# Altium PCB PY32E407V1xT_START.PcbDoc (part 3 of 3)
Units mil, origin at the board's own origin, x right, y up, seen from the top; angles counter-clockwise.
Board outline 1968.43 x 4717 mil, 2 copper layers (Top Layer, Bottom Layer), stack 21 mil thick; 210 components, 217 nets, 824 pads, 371 vias.
Unrouted connection lines stored in the file: 1.
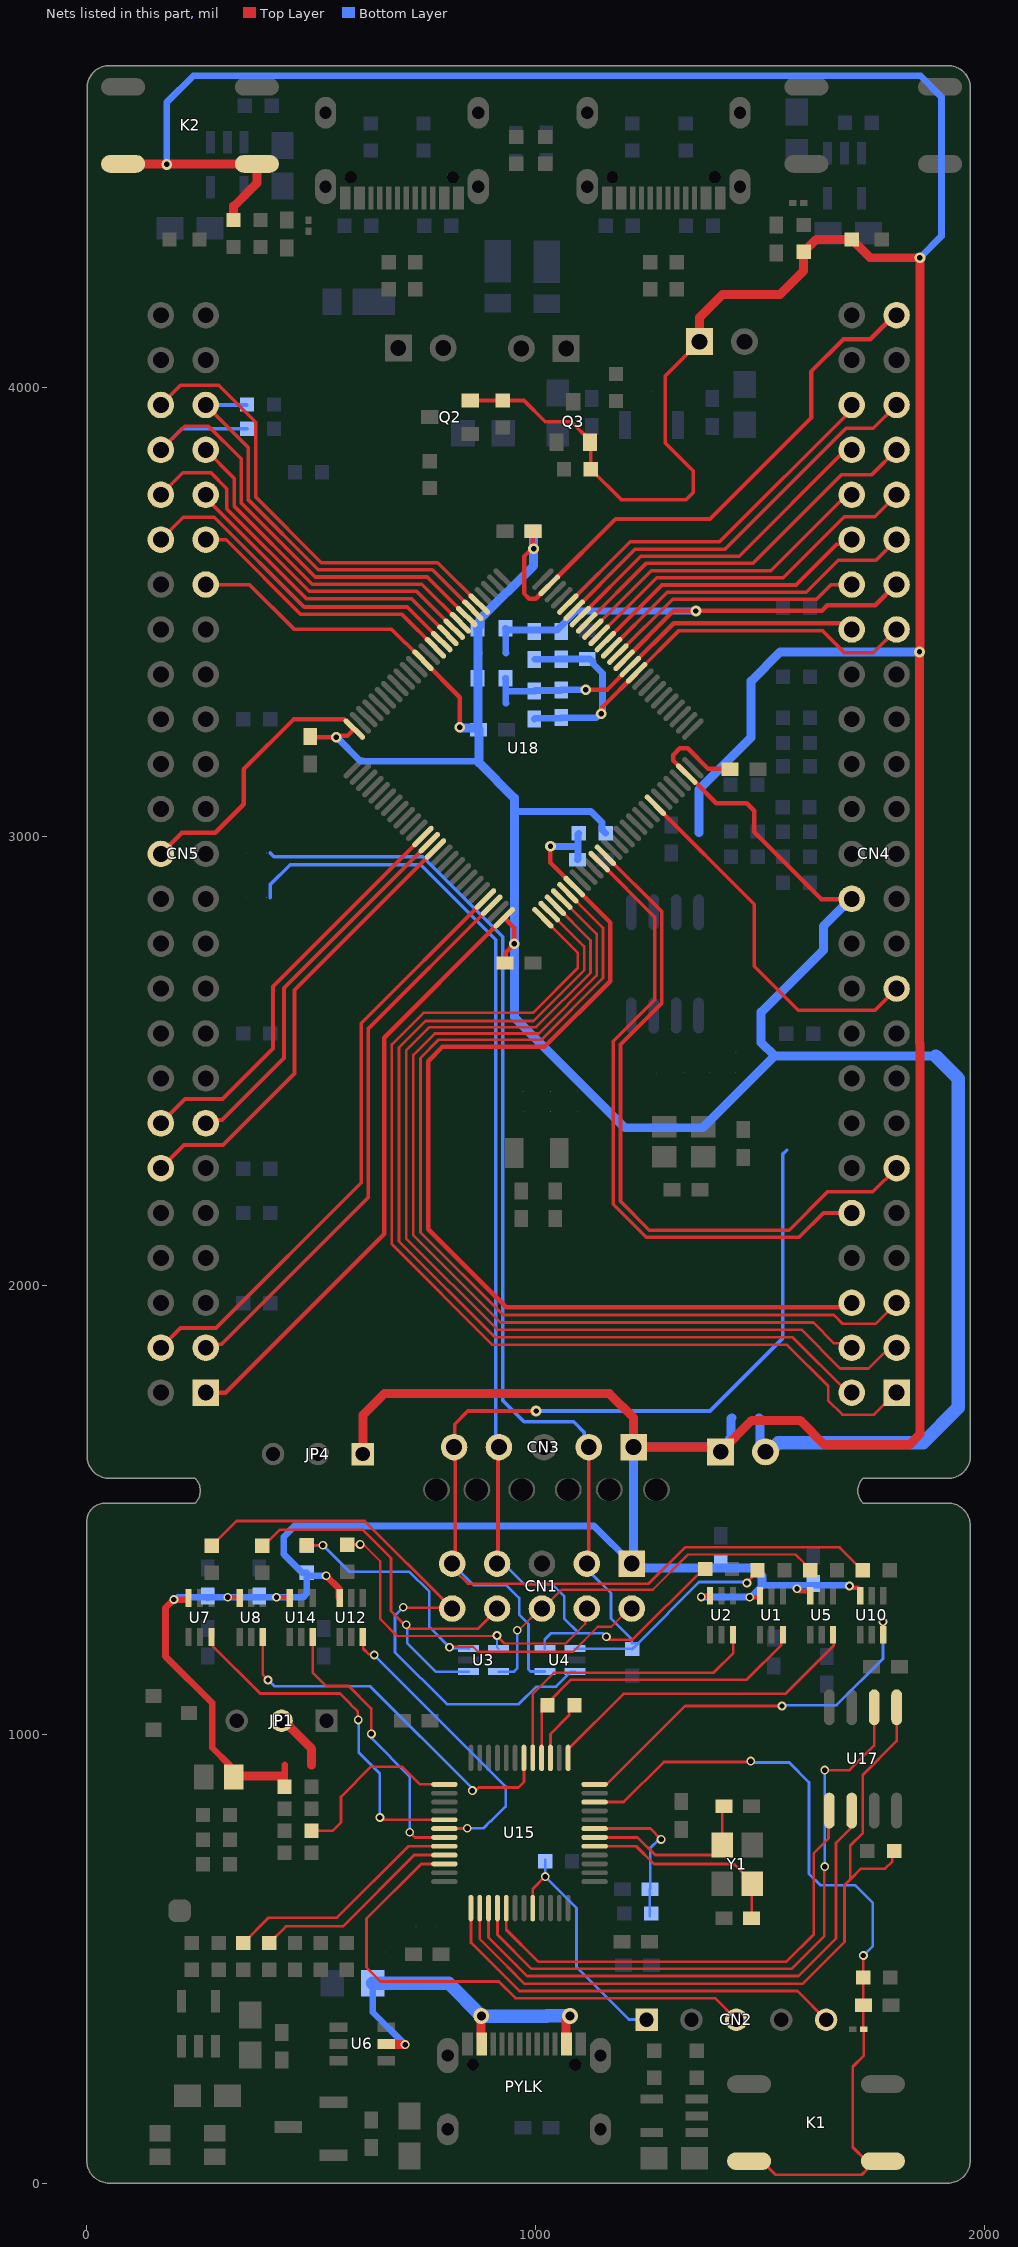
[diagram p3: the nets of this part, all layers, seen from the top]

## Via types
v1: diameter 24, hole 12, Top Layer to Bottom Layer, tented both sides, 208 vias
v2: diameter 19.68, hole 11.81, Top Layer to Bottom Layer, tented both sides, 106 vias
v3: diameter 19.68, hole 11.81, Top Layer to Bottom Layer, 37 vias
v4: diameter 35, hole 20, Top Layer to Bottom Layer, tented both sides, 16 vias
v5: diameter 30, hole 15, Top Layer to Bottom Layer, tented both sides, 2 vias
v6: diameter 40, hole 20, Top Layer to Bottom Layer, tented both sides, 2 vias

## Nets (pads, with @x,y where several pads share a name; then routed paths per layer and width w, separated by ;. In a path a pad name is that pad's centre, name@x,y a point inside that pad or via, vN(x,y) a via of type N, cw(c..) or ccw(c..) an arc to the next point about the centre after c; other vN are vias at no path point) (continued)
PD5: CN5.14 U18.87 | length 931.3
  Top Layer w9: CN5.14@165,2361 165,2364 168,2364 219,2415 302.59,2415 415.27,2527.68 415.27,2666.11 U18.87@748.9,2999.74
PD6: CN5.13 U18.88 | length 847.8
  Top Layer w9: CN5.13@265,2361 272.09,2368.09 300.76,2368.09 439.48,2506.82 439.48,2662.48 U18.88@762.82,2985.82
PD7: CN5.12 U18.89 | length 1015.2
  Top Layer w9: CN5.12@165,2261 217,2313 303.87,2313 462.52,2471.64 462.52,2657.68 U18.89@776.74,2971.9
PD8: CN5.46 U18.55 | length 1026.9
  Top Layer w8: CN5.46@165,3961 209,4005 293.71,4005 376.11,3922.6 376.11,3755.99 522.27,3609.84 781.87,3609.84 U18.55@874.17,3517.54
PD9: CN5.45 R81.1 U18.56 | length 944
  Top Layer w8: CN5.45@265,3961 360.11,3865.89 360.11,3749.36 515.64,3593.84 770.04,3593.84 U18.56@860.26,3503.62
  Bottom Layer w8: CN5.45@265,3961 R81.1@356,3961
PD10: CN5.44 R97.2 U18.57 | length 1148
  Top Layer w8: CN5.44@165,3861 218,3914 271.05,3914 344.11,3840.94 344.11,3742.74 509.01,3577.84 758.2,3577.84 U18.57@846.34,3489.7
  Bottom Layer w8: CN5.44@165,3861 212,3908 R97.2@357,3908
PD11: CN5.43 U18.58 | length 763.2
  Top Layer w8: CN5.43@265,3861 328.11,3797.89 328.11,3736.11 502.38,3561.84 746.36,3561.84 U18.58@832.42,3475.78
PD12: CN5.42 U18.59 | length 844.4
  Top Layer w8: CN5.42@165,3761 213.97,3809.97 276.67,3809.97 312.11,3774.53 312.11,3729.48 495.76,3545.84 734.52,3545.84 U18.59@818.5,3461.86
PD13: CN5.41 U18.60 | length 673.4
  Top Layer w8: CN5.41@265,3761 265,3753.97 489.13,3529.84 722.69,3529.84 U18.60@804.58,3447.94
PD14: CN5.40 U18.61 | length 761.1
  Top Layer w8: CN5.40@165,3661 215.03,3711.03 284.02,3711.03 484.11,3510.93 713.75,3510.93 U18.61@790.66,3434.02
PD15: CN5.39 U18.62 | length 611.5
  Top Layer w8: CN5.39@265,3661 265.52,3660.48 310.45,3660.48 476.45,3494.48 702.35,3494.48 U18.62@776.74,3420.1
PE0: CN5.4 U18.97 | length 1345.3
  Top Layer w8: CN5.4@165,1861 209,1905 287.86,1905 611.48,2228.63 611.48,2583.93 U18.97@888.1,2860.54
PE1: CN5.3 U18.98 | length 1265.6
  Top Layer w8: CN5.3@265,1861 272.65,1868.65 300.08,1868.65 627.48,2196.05 627.48,2572.09 U18.98@902.01,2846.63
PE2: CN4.1 U18.1 | length 2395.3
  Top Layer w6: U18.1@1016.15,2818.79 1016.15,2818.11 1094,2740.26 1094,2707.45 993.55,2607 750.12,2607 679.48,2536.36 679.48,2091.47 903.48,1867.48 1560.33,1867.48 1651.56,1776.25 1651.56,1743.27 1683,1711.83 1753.46,1711.83 1777.1,1735.47 1778.47,1735.47 CN4.1@1804,1761
PE3: CN4.2 U18.2 | length 2226.9
  Top Layer w6: U18.2@1030.06,2832.7 1108,2754.77 1108,2701.65 995.35,2589 754.75,2589 695.48,2529.74 695.48,2098.09 909.29,1884.29 1572.45,1884.29 1695.74,1761 CN4.2@1704,1761
PE4: CN4.3 U18.3 | length 2315.1
  Top Layer w6: U18.3@1043.99,2846.63 1122,2768.61 1122,2695.85 1001.15,2575 763.37,2575 711.48,2523.11 711.48,2104.72 915.1,1901.1 1591.85,1901.1 1678.09,1814.86 1741.07,1814.86 1786.95,1860.74 CN4.3@1804,1861
PE5: CN4.4 U18.4 | length 2166.6
  Top Layer w6: U18.4@1057.9,2860.54 1136,2782.44 1136,2690.05 1006.95,2561 775.38,2561 727.48,2513.11 727.48,2111.35 921.73,1917.1 1618.58,1917.1 1664.92,1870.77 1694.23,1870.77 CN4.4@1704,1861
PE6: CN4.5 U18.5 | length 2255.1
  Top Layer w6: U18.5@1072.24,2874.05 1150,2796.29 1150,2684.25 1012.75,2547 784,2547 743.48,2506.48 743.48,2117.98 927.74,1933.72 1664.38,1933.72 1684,1914.09 1757.09,1914.09 CN4.5@1804,1961
PE7: CN4.38 U18.38 | length 584.9
  Top Layer w8: U18.38@1183.18,3406.18 1305.04,3528.04 1625.51,3528.04 1658.46,3561 CN4.38@1704,3561
PE8: CN4.39 U18.39 | length 758.8
  Top Layer w8: U18.39@1152.1,3402.94 1293.2,3544.04 1602.95,3544.04 1673.91,3615 1758,3615 CN4.39@1804,3661
PE9: CN4.40 U18.40 | length 642.6
  Top Layer w8: U18.40@1155.34,3434.02 1281.41,3560.04 1580.09,3560.04 1671.28,3651.23 1694.23,3651.23 CN4.40@1704,3661
PE10: CN4.41 U18.41 | length 792.3
  Top Layer w8: U18.41@1141.42,3447.94 1269.52,3576.04 1551.46,3576.04 1687.42,3712 1755,3712 CN4.41@1804,3761
PE11: CN4.42 U18.42 | length 724.7
  Top Layer w8: U18.42@1110.34,3444.7 1257.69,3592.04 1523.74,3592.04 1692.7,3761 CN4.42@1704,3761
PE12: CN4.43 U18.43 | length 849.9
  Top Layer w8: U18.43@1113.64,3475.78 1245.9,3608.04 1483.57,3608.04 1681.53,3806 1749,3806 CN4.43@1804,3861
PE13: CN4.44 U18.44 | length 758.1
  Top Layer w8: U18.44@1099.66,3489.7 1234.01,3624.04 1453.3,3624.04 1690.26,3861 CN4.44@1704,3861
PE14: CN4.45 U18.45 | length 932
  Top Layer w8: U18.45@1068.58,3486.46 1222.16,3640.04 1422.26,3640.04 1691.49,3909.27 1752.27,3909.27 CN4.45@1804,3961
PE15: CN4.46 U18.46 | length 821.9
  Top Layer w8: U18.46@1071.88,3517.54 1210.38,3656.04 1409.46,3656.04 1704,3950.58 CN4.46@1704,3961
PF2: CN4.19 U18.19 | length 821.9
  Top Layer w8: U18.19@1270.35,3065.49 1486.87,2848.97 1486.87,2710.72 1584.59,2613 1756,2613 CN4.19@1804,2661
PF3: CN4.10 U18.10 | length 1437.1
  Top Layer w8: U18.10@1141.42,2944.06 1265.25,2820.23 1265.25,2770.06 1265.24,2697.91 1265.25,2636.18 1173,2543.93 1173,2180.37 1246.61,2106.76 1586.76,2106.76 1641,2161 CN4.10@1704,2161
PF4: CN4.11 U18.11 | length 1560.2
  Top Layer w8: U18.11@1155.34,2957.98 1281.25,2832.08 1281.25,2763.43 1281.24,2704.54 1281.25,2628.75 1189,2536.5 1189,2187 1253.24,2122.76 1564.76,2122.76 1650.11,2208.11 1751.11,2208.11 CN4.11@1804,2261
PYLK_BOOT0: CN2.1 R27.1 U15.44 | length 552.1
  Top Layer w6: U15.44@993.53,612.68 993.53,655.07 v2(1021.21,682.75)
  Bottom Layer w6: R27.1@1021.21,719.9 v2(1021.21,682.75) 1091,612.96 1091,481 1207.51,364.49 CN2.1@1245.51,364.49
PYLK_KEY: C5.2 K1.1 K1.2 R15.1 U11.1 U15.10 | length 1851.6
  Top Layer w6: U15.10@1131.32,848.9 1196.14,848.9 1285.44,938.2 1477.2,938.2 v2(1479,940) ; K1.2@1475.55,49 1504.25,49 1534.5,18.75 1726.36,18.75 1738.02,30.41 1738.02,34.51 K1.1@1752.51,49 ; R15.1@1727,453 1730,450 C5.2@1730,396 1730,343.54 U11.1@1730.54,343 1730.54,283.54 1706.3,259.3 1706.3,80 1737.3,49 K1.1@1752.51,49 ; R15.1@1729.77,458 1730,458.23 v2(1730,507) ; K1.1@1773.55,49 K1.1@1752.51,49
  Bottom Layer w6: v2(1479,940) 1482.06,936.94 1491.62,936.94 1491.69,936.88 1564.92,936.88 1609,892.8 1609,688.76 1633.9,663.86 1711.04,663.86 1751,623.9 1751,528 v2(1730,507)
PYLK_NRST: C23.2 R35.1 U15.7 | length 341.9
  Top Layer w6: U15.7@1131.32,789.84 1255.36,789.84 v2(1279.4,765.8)
  Bottom Layer w6: R35.1@1254.12,595 1254.12,654 C23.2@1255.12,655 1255.12,746 1274.92,765.8 v2(1279.4,765.8)
PYLK_OSCIN: C18.2 U15.5 Y1.3 | length 465.6
  Top Layer w6: U15.5@1131.32,750.47 1224.05,750.47 1263.42,711.1 1442.11,711.1 1482.59,670.63 Y1.3@1482.59,666.69 1481.12,665.22 C18.2@1481.12,590
PYLK_OSCOUT: C24.2 U15.6 Y1.1 | length 399.8
  Top Layer w6: U15.6@1131.32,770.16 1226.99,770.16 1266.36,730.79 1396.03,730.79 1415.66,750.41 Y1.1@1415.66,753.31 1415.66,836.54 C24.2@1419.12,840
PYLK_SPI_CS: R34.1 U15.38 U17.1 | length 1667.6
  Top Layer w5: U15.38@875.42,612.68 875.42,543.62 936.66,482.38
  Top Layer w6: 936.66,482.38 974.95,444.09 1594.51,444.09 1687.88,537.47 1687.88,663.88 1700.77,676.77 ; R34.1@1799,740 1794.62,735.62 1794.62,716.69 1778.36,700.42 1724.42,700.42 1700.77,676.77 ; U17.1@1804,1060 1804,985 1728.69,909.69 1728.69,780.01 1700.77,752.09 1700.77,676.77
PYLK_SPI_MISO: U15.40 U17.2 | length 1437.2
  Top Layer w6: U15.40@914.79,612.68 914.79,553.3 990.8,477.3 1570,477.3 1642.9,550.2 1642.9,703.9 v2(1644,705) ; v2(1644,920) 1699,920 1754,975 U17.2@1754,1060
  Bottom Layer w6: v2(1644,705) v2(1644,920)
PYLK_SPI_MOSI: U15.41 U17.5 | length 1077.9
  Top Layer w6: U15.41@934.47,612.68 934.47,564.49 1005.66,493.3 1558.42,493.3 1619.53,554.41 1619.53,735.09 1652.13,767.69 1652.13,828.13 U17.5@1654,830
PYLK_SPI_SCK: U15.39 U17.6 | length 1208.9
  Top Layer w6: U15.39@895.1,612.68 895.1,547.36 955.32,487.14 981.17,461.3 1585.07,461.3 1669.21,545.44 1669.21,758.06 1700.94,789.79 1700.94,826.94 U17.6@1704,830
SWD_SCK: CN2.5 U15.37 | length 939.3
  Top Layer w6: U15.37@855.73,612.68 855.73,535.75 963.48,428 1583,428 CN2.5@1647,364
SWD_SDA: CN2.3 U15.34 | length 1204.8
  Top Layer w6: U15.34@796.68,711.1 745.11,711.1 623.05,589.04 623.05,480.71 654.57,449.2 917.75,449.2 954.95,412 1399,412 CN2.3@1447,364
T_RESET: CN1.9 CN3.5 R17.2 R39.1 U4.4 | length 2927.6
  Top Layer w6: CN1.9@821.78,1362.78 849.2,1335.36 1251.91,1335.36 1332.99,1416.44 1677.06,1416.44 R17.2@1728.49,1365
  Top Layer w8: CN1.9@814,1380 821,1387 821,1636.82 CN3.5@818.26,1639.56 819.51,1640.82 819.51,1690.51 849,1720 v1(1001,1720)
  Bottom Layer w6: CN1.9@814,1380 862.22,1331.78 935.02,1331.78 963.1,1303.69 963.1,1266.42 984.15,1245.37 984.15,1144.31 988.61,1139.85 1020.09,1139.85 U4.4@1020.54,1139.41
  Bottom Layer w8: CN1.9@814,1380 CN1.9@823.04,1389.04 ; CN3.5@818.26,1639.56 CN3.5@823.04,1634.78 ; v1(1001,1720) 1388.26,1720 1550,1881.74 1550,2291.74 R39.1@1559.26,2301
T_RESETa: U10.3 U15.12 | length 870.1
  Top Layer w6: U15.12@1131.32,888.27 1157.79,888.27 1332.47,1062.96 1420.53,1062.96 v2(1548.91,1062.96) ; v2(1773.82,1250.7) 1774.08,1250.44 U10.3@1774.08,1221.69
  Bottom Layer w6: v2(1548.91,1062.96) 1550.65,1064.7 1670.4,1064.7 1773.82,1168.11 v2(1773.82,1250.7)
T_RTCK_DTRa: U5.3 U15.13 | length 731.2
  Top Layer w6: U15.13@1072.27,947.32 1072.27,966.57 1195.7,1090 1555.99,1090 1664.18,1198.19 1664.18,1220.16 U5.3@1662.66,1221.69
T_RTCK_VCP_DTR: CN1.6 R9.2 U3.5 | length 868.3
  Top Layer w5: v2(958.81,1231.67) 962.24,1231.67 1010.57,1280 CN1.6@1014,1280 1015.63,1280 1057.49,1321.86 1260.73,1321.86 1339.3,1400.44 1578.98,1400.44 1599.35,1380.07 1599.35,1377 R9.2@1611.35,1365
  Bottom Layer w6: U3.5@917.46,1139.41 951.51,1139.41 958.81,1146.71 v2(958.81,1231.67)
T_TCK_SWCLK: CN1.7 CN3.4 R6.2 R38.1 U4.5 | length 2745.1
  Top Layer w6: CN1.7@919,1390 CN1.7@920.35,1391.35 ; v2(1157.5,1217.32) 1164.14,1210.69 1215.96,1210.69 1370.28,1365 R6.2@1377.06,1365
  Top Layer w8: CN1.7@914,1380 916.13,1382.13 916.13,1637.43 CN3.4@918.26,1639.56
  Bottom Layer w6: CN1.7@921.5,1387.5 974.47,1334.53 1036.65,1334.53 1063.6,1307.57 1063.6,1257.54 1096.14,1225 ; U4.5@1020.54,1190.59 1020.54,1211.54 1034,1225 1096.14,1225 ; v2(1157.5,1217.32) 1149.82,1225 1096.14,1225
  Bottom Layer w8: 409,2864 409,2892.89 453.11,2937 743.71,2937 910.9,2769.82 910.9,1873.73 911,1873.63 911,1841.37 910.9,1841.27 910.9,1646.93 CN3.4@918.26,1639.56 CN3.4@916.79,1638.1 ; CN1.7@914,1380 CN1.7@916.79,1382.79
T_TCK_SWCLKa: U2.3 U15.17 | length 668.1
  Top Layer w5: U15.17@993.53,947.32 993.53,1089.76 1040.77,1137
  Top Layer w6: 1040.77,1137 1146.62,1137 1396.43,1137 1440.41,1180.98 1440.41,1221.08 U2.3@1439.8,1221.69
T_TDI_VCP_TX: CN1.4 R21.2 U3.4 | length 783.1
  Top Layer w5: R21.2@580.63,1422.11 616.9,1422.11 653.54,1385.48 653.54,1256.62 691.29,1218.86 v2@914,1218.86 ; R21.2@580.63,1425.11 R21.2@582.13,1423.61 ; v2@914.02,1218.86 930.78,1202.11 1066.76,1202.11 1110.56,1245.9 1110.56,1276.56 CN1.4@1114,1280
  Bottom Layer w5: v2@914.06,1219.94 914.06,1194 U3.4@917.46,1190.59
  other v2: 914,1220
  other v3: 608.96,1422.98
T_TDI_VCP_TXa: U12.3 U15.30 | length 672.4
  Top Layer w6: U12.3@614.71,1216.69 615.93,1215.47 615.93,1190.37 628.24,1178.06 638.56,1178.06 v2(640.31,1176.31) ; U15.30@796.68,789.84 847.02,789.84 v2(847.76,790.58)
  Bottom Layer w6: v2(640.31,1176.31) 933.09,883.53 933.09,838.92 900.56,806.38 899.71,806.38 883.91,790.58 v2(847.76,790.58)
T_TDO_SWO: CN1.10 R12.2 U4.3 | length 1333.3
  Top Layer w6: R12.2@278.66,1420.08 333.47,1474.9 619.1,1474.9 CN1.10@807.51,1286.49 ; v2(704.87,1282.75) 705.54,1282.08 803.1,1282.08 CN1.10@807.51,1286.49 ; CN1.10@814,1280 CN1.10@807.51,1286.49
  Bottom Layer w6: v2(704.87,1282.75) 686.83,1264.72 686.83,1182.08 802.06,1066.86 962.29,1066.86 1001.42,1105.99 1045.45,1105.99 1078.88,1139.41 U4.3@1087.46,1139.41 U4.3@1085.15,1137.1
T_TDO_SWOa: U7.3 U15.29 | length 807.7
  Top Layer w6: U7.3@278.14,1216.69 278.14,1198.86 386.46,1090.54 564.08,1090.54 570.63,1084 571.01,1084 588,1067.01 588,1066.63 603.93,1050.7 603.93,1032.69 v2(604.62,1032) ; v2(652.88,814.33) 657.68,809.53 740.55,809.53 U15.29@796.68,809.53
  Bottom Layer w6: v2(604.62,1032) 605.95,1030.68 605.95,958.93 652.88,912 v2(652.88,814.33)
T_TMS_SWDIO: CN1.3 CN3.2 R2.2 R37.1 R82.2 U4.1 | length 2855.4
  Top Layer w6: CN1.3@1118.37,1366.19 CN1.3@1124.56,1360 ; v2@1470.62,1338.31 1481.21,1348.9 1481.21,1352 R2.2@1494.21,1365
  Top Layer w8: CN1.3@1114,1380 1118.26,1384.26 CN3.2@1118.26,1639.56
  Bottom Layer w6: U4.1@1087.77,1190.29 1215.29,1190.29 R82.2@1225.38,1200.38 ; CN1.3@1122.59,1359.7 1167.86,1314.42 1167.86,1257.89 1214.27,1211.49 1214.27,1203 1222.75,1203 R82.2@1225.38,1200.38 ; R82.2@1215,1190 R82.2@1225.38,1200.38 ; v2(1470.43,1337.07) 1468.25,1339.25 1364.25,1339.25 R82.2@1225.38,1200.38
  Bottom Layer w8: 409,2963 417.28,2954.72 748.62,2954.72 926.9,2776.44 926.9,1880.36 927,1880.25 927,1834.75 926.9,1834.64 926.9,1743.26 974.16,1696 1084.55,1696 1108.49,1672.06 1108.49,1649.33 CN3.2@1118.26,1639.56 CN3.2@1118,1639.3 ; CN1.3@1114,1380 CN1.3@1118,1384
T_TMS_SWDIOa: R31.1 U1.3 U15.16 | length 723.8
  Top Layer w6: U15.16@1013.21,947.32 R31.1@1013.21,1067.37 ; R31.1@1026.46,1064.37 1026.46,1068.99 1079.12,1121.65 1135.7,1121.65 1470.22,1121.65 1547.34,1198.77 1547.34,1217.8 U1.3@1551.23,1221.69
T_TMS_SWDIOa_OUT: R31.2 U15.15 | length 143.2
  Top Layer w6: U15.15@1032.9,947.32 1032.9,1000.64 1074.82,1042.56 R31.2@1074.82,1073.16
T_TRST_RTSa: U8.3 U15.18 | length 840.3
  Top Layer w6: U8.3@391.86,1216.69 391.86,1132.86 v2(403.82,1120.9) ; v2(858.92,874.35) 862.83,870.44 873.54,881.16 961.39,881.16 973.84,893.6 U15.18@973.84,947.32
  Bottom Layer w6: v2(403.82,1120.9) 417.81,1106.91 630.65,1106.91 858.92,878.64 v2(858.92,874.35)
T_TRST_VCP_RTS: CN1.8 R13.2 U3.1 | length 935
  Top Layer w6: R13.2@391.3,1420.1 394.54,1420.1 430.24,1455.8 614.25,1455.8 677.58,1392.47 677.58,1274.56 708.4,1243.73 v2(711.86,1243.73) 720.6,1235 871.67,1235 919,1282.33 CN1.8@919,1290
  Bottom Layer w6: v2(711.86,1243.73) 714,1241.6 714,1202.6 777.19,1139.41 U3.1@850.54,1139.41
T_VCP_RX: CN1.2 R22.1 R25.2 U3.3 | length 1000.9
  Top Layer w5: v2(807.97,1193.74) 809.23,1195 860.42,1195 871.45,1183.97 1082.91,1183.97 1138.3,1239.36 1168.36,1239.36 CN1.2@1219,1290
  Top Layer w6: R25.2@490.2,1420.7 525.7,1420.7 v3(526,1421) ; R25.2@490.2,1431.85 R25.2@490.32,1431.97
  Bottom Layer w6: R22.1@490,1420 491,1421 v3(526,1421) 584.72,1362.28 718.26,1362.28 763.05,1317.5 763.05,1238.66 v2(807.97,1193.74) 807.23,1193 807.23,1191.77 849.36,1191.77 U3.3@850.54,1190.59
T_VCP_RXa: U14.3 U15.31 | length 636
  Top Layer w6: U14.3@503.28,1216.69 503.28,1137.29 532.27,1108.3 582.54,1108.3 633.4,1057.43 633.4,1001.38 v2(634,1000.78) ; v2(719.4,781.75) 730.99,770.16 U15.31@796.68,770.16
  Bottom Layer w6: v2(634,1000.78) 634,991.42 719.4,906.02 v2(719.4,781.75)
TVDD: C11.2 C12.2 C13.2 C14.2 CN1.1 CN3.1 JP2.1 JP3.1 JP4.1 K2.1 K2.2 LED2_PB5.1 Q2.2 Q3.2 R14.2 R16.2 R22.2 R33.2 R50.1 R51.1 R58.1 R59.2 R95.1 R98.1 U1.6 U2.6 U5.6 U7.6 U8.6 U10.6 U12.6 U14.6 | length 12757.1
  Top Layer w6: U8.6@340.67,1303.31 U8.6@343.56,1306.2 ; U14.6@452.1,1303.31 U14.6@454.99,1306.2
  Top Layer w8: Q2.2@854.55,3971.4 854.95,3971 R95.1@927,3971 974,3971 1021,3924 1078.94,3924 1121,3881.94 Q3.2@1121,3878 1123,3876 R98.1@1123,3818 1191.06,3749.94 1334.94,3749.94 1351,3766 1351,3814 1289,3876 1289,4026 JP3.1@1365,4102
  Top Layer w10: v2(314,1305) 338.98,1305 U8.6@340.67,1303.31 ; v3@424,1305 450.41,1305 U14.6@452.1,1303.31 ; v3(1476.88,1305.09) 1498.07,1305.09 1498.16,1305 1500.05,1306.89 U1.6@1500.05,1308.31 ; v2(1582.29,1324.06) 1587.61,1318.74 1611.47,1318.74 U5.6@1611.47,1308.31 ; v2@1707.68,1326.1 1717.91,1326.1 1722.9,1321.1 U10.6@1722.9,1308.31
  Top Layer w12: v2@1369.9,1306.9 U2.6@1388.01,1306.9
  Top Layer w15: v2(194,1300) 175.66,1281.66 175.66,1173.6 279.53,1069.73 279.53,969.95 319.52,929.96 319.52,912.95 R14.2@327.46,905 R14.2@329.24,906.78 ; v2@194.63,1299.37 U7.6@226.35,1299.37 ; 437.07,906.78 441.08,902.77 ; R16.2@441.08,874.02 441.08,902.77 ; 441.08,931.52 441.08,902.77 ; v3(533.28,1353.05) 561.84,1324.49 561.84,1305 U12.6@563.53,1303.31 ; v2(1369,1306) v2@1369.9,1306.9
  Top Layer w20: K2.2@81,4498 K2.1@379,4498 379,4455 328,4404 327,4404 R59.2@327,4373 ; R14.2@329.24,906.78 437.07,906.78 ; JP4.1@615,1624.13 615,1711 663,1759 1164,1759 1218.26,1704.74 CN3.1@1218.26,1639.56 1401.56,1639.56 JP2.1@1412,1629.13 1481.87,1699 1589,1699 1643,1645 1832.77,1645 1856,1668.23 1856,2538.57 1855,2539.57 v1(1855,3411) ; JP3.1@1365,4102 1365,4156 1416,4207 1544,4207 1597,4260 R51.1@1597,4302 1625,4330 LED2_PB5.1@1704,4330 1745,4289 v1(1856,4289) v1@1856,3411
  Bottom Layer w15: v1(178,4497) 178,4635 237.49,4694.49 1857,4694.49 1904.02,4647.47 1904.02,4337.02 v1(1856,4289) ; v2(194,1300) 197.79,1300 202.67,1304.88 C14.2@267.87,1304.88 ; C14.2@269,1303.74 C14.2@267.87,1304.88 ; v2@313.88,1304.88 C14.2@267.87,1304.88 ; v2(314,1305) v3(422.77,1305) 482,1305 490,1313 R22.2@490,1353.05 ; v3(533.28,1353.05) R22.2@490,1353.05 ; CN1.1@1214,1380 1130,1464 463,1464 439,1440 439,1400.76 479.76,1360 R22.2@490,1360 R22.2@490,1353.05 ; v2@1369.38,1305.62 v3@1476.36,1305.62 ; v3(1476.88,1305.09) 1478.15,1305.09 1480.49,1307.43 1481.09,1307.43 1505.58,1331.92 ; 1503.72,1331.92 1505.58,1331.92 ; v2(1699,1330) 1697.08,1331.92 1505.58,1331.92
  Bottom Layer w20: CN1.1@1217.94,1383.94 CN3.1@1217.94,1639.24 ; CN3.1@1218.26,1639.56 1401.56,1639.56 JP2.1@1412,1629.13 1432,1649.13 1432,1657.55 1435.3,1660.84 1435.3,1703.3 1437,1705 ; CN1.1@1221.04,1388.26 1242.46,1370 1485.9,1370 1503.72,1352.18 1503.72,1331.92 ; R50.1@1363.97,3008.78 1363.97,3104.6 1480,3220.63 1480,3346 1545,3411 v1(1855,3411)
TVDD*: JP1.2 R33.1 | length 129
  Top Layer w20: JP1.2@434,1030 438.73,1030 501.08,967.65 501.08,931.52
TVDD_DISCHARGE_EN: R18.2 U15.25 | length 404.9
  Top Layer w6: R18.2@500.53,784.78 547.51,784.78 566.48,803.75 566.48,860.55 633.58,927.66 702.61,927.66 742,888.27 U15.25@796.68,888.27
USB_DM: R10.2 U15.32 | length 536.9
  Top Layer w6: R10.2@349,535 405.4,591.4 557.28,591.4 716.36,750.47 U15.32@796.68,750.47
USB_DP: R11.2 U15.33 | length 471.3
  Top Layer w6: R11.2@406.5,535 443.45,571.95 570.73,571.95 729.56,730.79 U15.33@796.68,730.79
VBAT: C50.2 CN4.6 R79.2 U18.6 | length 2350.8
  Top Layer w10: v1(1033,2978) 1033,2941.12 U18.6@1085.74,2888.38 ; U18.6@1086.39,2888.38 1086.39,2887.73 1166,2808.12 1166,2677.62 1019.38,2531 792.05,2531 760.48,2499.44 760.48,2125.02 934.69,1950.81 1673.79,1950.81 1674.2,1951.23 1694.23,1951.23 CN4.6@1704,1961
  Bottom Layer w15: v1(1033,2978) 1033.5,2977.5 1094.5,2977.5 ; C50.2@1093,2948 1094.5,2949.5 1094.5,2977.5 ; R79.2@1096,3007 1094.5,3005.5 1094.5,2977.5
VBUS_PYLK: F1.1 PYLK.A4 PYLK.A9 PYLK.B4 PYLK.B9 U6.5 | length 780.7
  Top Layer w10: PYLK.A4@873.81,309.89 PYLK.B9@885.62,309.89 ; PYLK.B4@1062.78,309.88 PYLK.A9@1074.6,309.88
  Top Layer w20: U6.5@667.15,310 667.98,309.17 708.58,309.17 v2(709.2,308.55) ; PYLK.A4@878.73,327 v4@878.73,372.23 ; PYLK.B4@1068.05,329.68 v4@1068.05,363.49
  Bottom Layer w15: F1.1@636.98,445 636.98,380.77 v2(709.2,308.55)
  Bottom Layer w20: v4@1076.13,372.01 v4(1076.62,372.5)
  Bottom Layer w30: F1.1@636.98,445 646.89,445 651.8,445 806.5,445 v4(879,372.5) ; v4@879.49,372.01 1024.68,372.01 ; 1024.68,373.41 v4@1075.72,373.41
VCCA: C42.2 C43.2 CN4.37 L2.2 R44.2 U18.37 | length 1171.2
  Top Layer w10: U18.37@1197.15,3392.27 1307.91,3503.03 1355.97,3503.03 v1(1357,3502) ; v1@1357.13,3502.13 1637.13,3502.13 1649.8,3514.8 1756.16,3514.8 1802.36,3561 CN4.37@1804,3561
  Bottom Layer w15: L2.2@933.01,3463.5 L2.2@933.51,3463 ; 934,3408.5 933.51,3408.99 L2.2@933.51,3463 ; C43.2@1045.53,3460.03 998.09,3460.03 936.48,3460.03 L2.2@933.51,3463 ; C43.2@1049,3460.57 1090.43,3502 v1(1357,3502)
VDD: C26.2 C30.2 C31.2 C32.2 C33.2 C41.2 CN4.24 CN4.49 CN5.1 CN5.26 CN5.37 JP2.2 L2.1 L3.1 R44.1 R45.1 R58.2 R79.1 U18.24 U18.49 U18.64 U18.75 U18.100 | length 9629.9
  Top Layer w8: CN5.37@265,3561 362.29,3561 461.46,3461.83 678.17,3461.83 710.04,3429.96 711.19,3429.96 U18.64@748.9,3392.26
  Top Layer w10: CN5.26@165,2961 212,3008 286.55,3008 350,3071.45 350,3150 461.5,3261.5 572.94,3261.5 U18.75@595.3,3239.15 ; CN5.1@265,1761 309,1761 662.48,2114.48 662.48,2551.28 U18.100@911.82,2800.62 ; C30.2@498,3223 500,3221 v1(556,3221) 558.68,3223.68 580.32,3223.68 U18.75@595.79,3239.15 ; U18.64@748.9,3392.26 831,3310.17 v1(831,3243) ; U18.100@911.76,2800.69 U18.100@929.85,2818.79 952.51,2796.13 v1(952.51,2760.8) 933.85,2742.14 933.85,2719.85 C32.2@932,2718 ; C31.2@994,3680 994,3643.47 974.18,3623.65 974.18,3541.28 985.92,3529.54 999.82,3529.54 1029.57,3559.3 U18.49@1030.06,3559.3 ; U18.49@1030.06,3559.3 1177.87,3707.04 1388.33,3707.04 1613.48,3932.19 1613.48,4035.5 1685.58,4107.61 1745.43,4107.61 1798.83,4161 CN4.49@1804,4161 ; C41.2@1437,3151 1383.9,3151 1338.89,3196.02 1321.27,3196.02 1306.63,3181.38 1306.63,3169.09 1336.3,3139.43 U18.24@1336.3,3138.94 1336.79,3138.94 1355.79,3119.94 1356.39,3119.94 1402.33,3074 1470,3074 1487,3057 1487,3010 1636.49,2860.51 CN4.24@1703.51,2860.51
  Bottom Layer w15: v1(556,3221) 609.68,3167.32 874.04,3167.32 ; 952.65,3055.33 1123.18,3055.33 1147.5,3031.01 1147.5,3015.5 R79.1@1156,3007
  Bottom Layer w20: v1(831,3243) 832.08,3243 833.72,3241.36 C33.2@869.64,3241.36 ; C33.2@871.51,3239.99 871.51,3462.01 L2.1@870.02,3463.5 875.77,3469.24 875.77,3483.36 995.31,3602.9 C26.2@995.31,3678.69 ; C33.2@874.04,3238.5 874.04,3163.78 952.65,3085.17 952.65,3055.33 v1@952.65,2760.94 ; v1@952.81,2760.5 952.81,2597.17 1198.97,2351 1372.16,2351 1532.14,2510.98 ; 1497,1705 1499.76,1702.24 1499.76,1652.19 JP2.2@1512,1639.95 ; JP2.2@1512,1629.13 JP2.2@1522.82,1629.13 ; 1577.74,2510.74 1891.26,2510.74 ; 1577.98,2510.98 1532.14,2510.98 ; CN4.24@1702.05,2861 1640.74,2799.69 1640.74,2746.86 1502.37,2608.49 1502.37,2540.76 1532.14,2510.98
  Bottom Layer w30: JP2.2@1522.82,1629.13 1522.82,1631.83 1540.44,1649.44 1863.13,1649.44 1941.43,1727.74 1941.43,2460.57 1891.26,2510.74
  other v1: 995.31,3640.8
VREF+: C44.2 C45.2 CN4.36 L3.2 R45.2 U18.36 | length 893.1
  Top Layer w10: v1@1111.74,3326.32 1159,3326.32 U18.36@1211.02,3378.34 1307.33,3474.66 1677.07,3474.66 1690.73,3461 CN4.36@1704,3461
  Bottom Layer w15: L3.2@933.01,3352.5 933.51,3352 933.51,3324.5 ; 934,3296.5 933.51,3296.99 933.51,3324.5 ; C45.2@1055.5,3325 998.5,3325 C44.2@997,3323.5 934.51,3323.5 933.51,3324.5 ; C45.2@1057.07,3326.42 v1@1111.42,3326.42
  other v1: 1111.53,3326.53
VSSA: C42.1 C43.1 C44.1 C45.1 CN4.35 L1.1 U18.35 | length 1190.3
  Top Layer w8: U18.35@1224.94,3364.42 1318.17,3457.66 1639.34,3457.66 1688,3409 1752,3409 CN4.35@1804,3461
  Top Layer w10: v1@1145.92,3273.08 1148.68,3275.83 1148.68,3288.26 U18.35@1224.84,3364.42
  Bottom Layer w15: C44.1@997,3261.5 998.5,3263 1055.5,3263 C45.1@1057,3264.5 1135.06,3264.5 v1@1144.28,3273.71 ; C42.1@998.09,3394.57 1049,3394.57 1049.72,3395.28 1109.28,3395.28 L1.1@1110,3396 ; L1.1@1110.01,3396 L1.1@1112.95,3396 ; L1.1@1117,3395.24 1121.22,3395.24 1128.2,3388.26 1128.2,3384.04 1148.83,3363.41 1148.83,3282.2 1147.72,3281.09 1147.72,3274.72 v1(1146,3273)
pads on no net: PYLK. PYLK.A8 PYLK.B8 U15.42 U15.45 USB1. USB1.A8 USB1.B8 USB2. USB2.A8 USB2.B8

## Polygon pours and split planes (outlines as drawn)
GND on Bottom Layer "NONET_L-01_P-001" (solid, remove dead copper, pour order 3): 0.68,4717 1981.35,4717 1981.35,0 -9.68,0
GND on Top Layer "NONET_L-01_P-001" (solid, remove dead copper, pour order 4): 0.68,4717 1980.92,4717 1980.92,0 -9.68,0

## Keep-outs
Keep-Out Layer:
  lines w8: 0,50 ccw(c50,50) 50,0 177.74,0 1791.91,0 1918,0 ccw(c1918,50) 1968,50 1968,1465 ccw(c1918,1465) 1918,1515 1829,1515 1729,1515 cw(c1756.5,1542.5) 1729,1570 1829,1570 1918.43,1570 ccw(c1918.43,1620) 1968.43,1620 1968.43,4667 ccw(c1918.43,4667) 1918.43,4717 1820.65,4717 1791.91,4717 177.74,4717 149,4717 50.57,4717 ccw(c50.57,4667) 0.57,4667 0.57,1620 ccw(c50.57,1620) 50.57,1570 100,1570 141.5,1570 241.5,1570 cw(c214,1542.5) 241.5,1515 141.5,1515 41,1515 ccw(c41,1474) 0,1474 0,50 ; 314,1515 cw(c341.5,1542.5) 314,1570 664,1570 684,1570 cw(c656.5,1542.5) 684,1515 664,1515 314,1515 ; 1359,1515 cw(c1386.5,1542.5) 1359,1570 1379,1570 1659,1570 cw(c1631.5,1542.5) 1659,1515 1379,1515 1359,1515

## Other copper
Top Layer:
  region net GND: 564.94,4445.05 586.94,4445.05 586.94,4351.55 564.94,4351.55
  region net GND: 816.91,4445.05 838.91,4445.05 838.91,4351.55 816.91,4351.55
  region net GND: 1399.91,4445.05 1421.91,4445.05 1421.91,4351.55 1399.91,4351.55
  region net GND: 1148,4446.5 1170,4446.5 1170,4353 1148,4353
  region net 5V_USB2_START: 1368.98,4445.99 1389.98,4445.99 1389.98,4305.99 1368.98,4305.99
  region net 5V_USB2_START: 1180,4446 1201,4446 1201,4306 1180,4306
  region net 5V_USB1_START: 785.98,4445.99 806.98,4445.99 806.98,4305.99 785.98,4305.99
  region net 5V_USB1_START: 597,4446 618,4446 618,4306 597,4306
  pour cut-out: 989,2210 991,2212 1024,2212 1024,2177.5 989,2177.5
  pour cut-out: 1754,1370 1764,1370 1764,1360 1754,1360
  pour cut-out: 374,490 384,490 384,480 374,480
  pour cut-out: 374,525 384,525 384,515 374,515
  pour cut-out: 429,525 434.5,525 434.5,503 429,503
  pour cut-out: 429,490 439,490 439,480 429,480
  region net 5V_USB_CHGR: 484,235 494,245 519,245 564,200 609,200 629,180 759,180 759,120 614,120 614,140 589,165 534,165 499,200 484,215
  region net 3V3_PYLK: 339,315 389,315 409,295 454,295 459,290 459,250 444,235 444,165 461.5,147.5 454,140 392.39,140 392.39,153.49 404,165.1 404,230 379,255 339,255
  region net 3V3_PYLK: 1194,155 1204,165 1224,165 1234,155 1234,130 1239,125 1284,125 1289,120 1289,105 1284,100 1229,100 1194,135
  region net 3V3_USB_PYLK: 1326.5,120 1399,120 1414,135 1434,135 1444,125 1444,105 1429,90 1414,90 1389,65 1389,25 1324,25 1324,118.33
  pour cut-out: 489,495 499,495 499,485 489,485
  pour cut-out: 544,495 554,495 554,485 544,485
  pour cut-out: 1726.43,1037 1736.43,1037 1736.43,1027 1726.43,1027
  pour cut-out: 1774,1075 1784,1075 1784,1065 1774,1065

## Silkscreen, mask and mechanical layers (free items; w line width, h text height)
Top Overlay:
  drawing of 1057 lines, arcs and shapes, not listed
  text "NRST" at 1694,4412.64 h60
  text "USER_PB6" at 61,4410.66 h60
  text "USB1" at 833,4339.64 h60
  text "USB2" at 1008,4339.64 h60
  text "50" at 1684,4224.54 h50
  text "49" at 1785,4224.54 h50
  text "52" at 246,4220.54 h50
  text "51" at 147,4219.54 h50
  text "VDD" at 1861,4159.1 h50
  text "B13" at 330,4151.63 h50
  text "B12" at 15,4150.1 h50
  text "B11" at 1531,4147.1 h50
  text "B10" at 1861,4058.06 h50
  text "B15" at 330,4052.45 h50
  text "B14" at 15,4050.91 h50
  text "GND" at 1531,4046.29 h50
  text "3V3" at 1425,4006.54 h50
  text "5V" at 926,4005.54 h50
  text "VDD*" at 1296,4005 h50
  text "VBUS1" at 610,4001.54 h50
  text "5V" at 779,4001.54 h50
  text "VBUS2" at 1001,3999.54 h50
  text "E14" at 1861,3957.56 h50
  text "D9" at 330,3951.66 h50
  text "D8" at 15,3950.66 h50
  text "E15" at 1531,3945.94 h50
  text "E12" at 1861,3857.06 h50
  text "D10" at 15,3850.51 h50
  text "D11" at 330,3850.97 h50
  text "E13" at 1531,3845.6 h50
  text "E10" at 1861,3756.02 h50
  text "D13" at 330,3752.43 h50
  text "D12" at 15,3750.9 h50
  text "E11" at 1531,3745.79 h50
  text "E8" at 1861,3654.99 h50
  text "D15" at 330,3651.18 h50
  text "D14" at 15,3649.64 h50
  text "E9" at 1531,3645.44 h50
  text "VCCA" at 1855,3556.83 h45
  text "GND" at 7,3550.92 h50
  text "VDD" at 330,3550.38 h50
  text "E7" at 1531,3545.74 h50
  text "VSSA" at 1858,3458.67 h45
  text "C6" at 17,3453.74 h50
  text "C7" at 330,3451.74 h50
  text "VREF+" at 1502,3446.04 h50
  text "B1" at 1861,3358.17 h50
  text "C8" at 17,3352.48 h50
  text "C9" at 330,3350.48 h50
  text "B2" at 1531,3346.23 h50
  text "C5" at 1861,3256.67 h50
  text "A8" at 16.96,3251.76 h50
  text "A9" at 329.96,3249.76 h50
  text "B0" at 1531,3245.88 h50
  text "A7" at 1860.96,3156.28 h50
  text "A10" at 16.96,3151.51 h50
  text "A11" at 329.96,3148.97 h50
  text "C4" at 1531,3145.08 h50
  text "A5" at 1860.96,3055.35 h50
  text "A12" at 16.96,3050.71 h50
  text "GND" at 330,3049.25 h50
  text "A6" at 1530.96,3044.73 h50
  text "A3" at 1860.96,2954.32 h50
  text "VDD" at 7,2949.53 h50
  text "A13" at 329.96,2950.07 h50
  text "A4" at 1530.96,2945.03 h50
  text "GND" at 1861,2852.82 h50
  text "A14" at 18.96,2848.85 h50
  text "A15" at 329.96,2849.38 h50
  text "VDD" at 1524,2845 h50
  text "A1" at 1860.96,2752.32 h50
  text "C10" at 19,2750.2 h50
  text "C11" at 330,2750.2 h50
  text "A2" at 1530.96,2745.52 h50
  text "F2" at 1861,2651.82 h50
  text "C12" at 19,2648.94 h50
  text "D0" at 330,2648.94 h50
  text "A0" at 1530.96,2645.17 h50
  text "C2" at 1861,2550.32 h50
  text "D1" at 19,2547.69 h50
  text "D2" at 330,2547.69 h50
  text "C3" at 1531,2544.36 h50
  text "C0" at 1861,2448.82 h50
  text "D3" at 19,2447.97 h50
  text "D4" at 330,2447.43 h50
  text "C1" at 1531,2443.56 h50
  text "F1" at 1861,2348.32 h50
  text "D5" at 19,2347.25 h50
  text "D6" at 330,2347.25 h50
  text "F5" at 1531,2343.32 h50
  text "F4" at 1861,2247.93 h50
  text "B3" at 330,2246.53 h50
  text "D7" at 19,2245.99 h50
  text "F0" at 1531,2242.97 h50
  text "B4" at 19,2145.74 h50
  text "B5" at 330,2146.27 h50
  text "C15" at 1861,2146.43 h50
  text "F3" at 1531,2142.63 h50
  text "B6" at 19,2046.12 h50
  text "B7" at 330,2045.59 h50
  text "C13" at 1861,2044.93 h50
  text "C14" at 1531,2041.82 h50
  text "PY32E407-START V2.2" at 788,1991.17 h65
  text "B8" at 19,1947.05 h50
  text "B9" at 330,1947.05 h50
  text "E6" at 1861,1943.89 h50
  text "VBAT" at 1502,1942.12 h50
  text "2025-11" at 798.95,1862.47 h65
  text "E0" at 19,1845.79 h50
  text "E1" at 330,1845.26 h50
  text "E4" at 1861,1843.5 h50
  text "E5" at 1531,1841.88 h50
  text "GND" at 7,1745.54 h50
  text "VDD" at 330,1745 h50
  text "E2" at 1862,1743 h50
  text "E3" at 1531,1741.54 h50
  text "VDD*" at 1199,1710.51 h45
  text "NRST" at 729,1710.48 h45
  text "SWC" at 859,1710.48 h45
  text "GND" at 969,1710.48 h45
  text "SWD" at 1084,1710.48 h45
  text "VDD*" at 1366,1679.51 h45
  text "VDD" at 1475,1679.51 h45
  text "VDD*" at 608,1675 h50
  text "GND" at 341,1673.54 h50
  text "BOOT0" at 450,1673.54 h50
  text "99" at 145,1665.54 h50
  text "100" at 234,1664.54 h50
  text "2" at 1690.96,1645 h50
  text "1" at 1799,1642 h50
  text "IDD" at 1565,1622 h45
  text "NRST" at 769,1445.43 h40
  text "SWC" at 889,1445.43 h40
  text "GND" at 995.86,1445.43 h40
  text "SWD" at 1095.31,1445.43 h40
  text "VDD*" at 1189,1445.46 h40
  text "DTR" at 995.86,1175.88 h40
  text "TX" at 1095.31,1175.88 h40
  text "RX" at 1189,1175.88 h40
  text "SWO" at 769,1175.43 h40
  text "RTS" at 889,1175.43 h40
  text "5V" at 289,1075.64 h60
  text "3V3" at 509,1075.64 h60
  text "VDD*" at 364,1075 h60
  text "DIO" at 1457.46,413 h50 r90
  text "GND" at 1561.46,410 h50 r90
  text "BT0" at 1262.18,408.44 h50 r90
  text "VDD" at 1361,408 h50 r90
  text "CLK" at 1660.46,407 h50 r90
  text "PY-LINK OB V2.1" at 745,388.17 h65
Bottom Overlay:
Mechanical 1:
  lines w6: 314,1515 664,1515 684,1515 ; 314,1570 664,1570 684,1570 ; 1359,1515 1379,1515 1659,1515 ; 1359,1570 1379,1570 1659,1570
  lines w8: 314,1515 cw(c341.5,1542.5) 314,1570 ; 684,1515 ccw(c656.5,1542.5) 684,1570 ; 1359,1515 cw(c1386.5,1542.5) 1359,1570 ; 1659,1515 ccw(c1631.5,1542.5) 1659,1570

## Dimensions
1981.35,0 to 1902,4716 on Mechanical 1
177.74,0 to 94,1505 on Mechanical 1
0,-2 to 1967,-57 on Mechanical 1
